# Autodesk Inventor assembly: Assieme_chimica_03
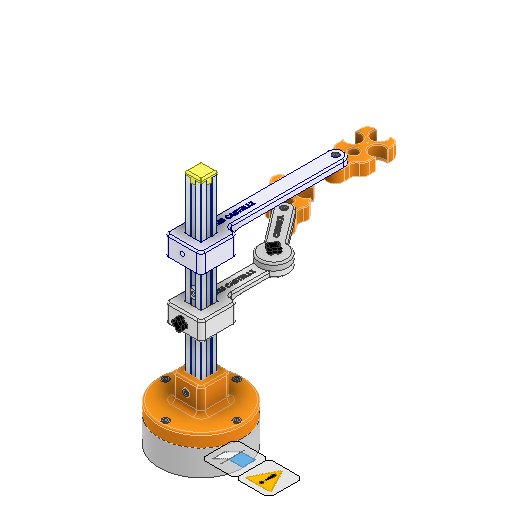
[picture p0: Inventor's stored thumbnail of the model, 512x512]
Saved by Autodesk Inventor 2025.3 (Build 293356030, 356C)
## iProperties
Created: 2025-09
Part Number: Assieme_chimica_03
Document SubType Name: Assembly
Designer: Ryzen5700u
Author: Ryzen5700u
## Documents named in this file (16)
- C:\Users\R5800u\Desktop\chimica_finale\Assieme_chimica_03.iam
- C:\Users\R5800u\Desktop\chimica_finale\tslot-20x20-3_MIR1.ipt
- C:\Users\R5800u\Desktop\chimica_finale\base_ferro.ipt
- C:\Users\R5800u\Desktop\chimica_finale\braccio.ipt
- C:\Users\R5800u\Desktop\chimica_finale\tappo_2020.ipt
- C:\Users\R5800u\Desktop\chimica_finale\vite_blocco.ipt
- C:\Users\R5800u\Desktop\chimica_finale\porta_sensore.ipt
- C:\Users\R5800u\Documents\Inventor\Content Center Files\R2025\it-IT\AS 1420\AS 1420 - 1973 - M5 x 20.ipt
- C:\Users\R5800u\Desktop\chimica_finale\AS 1420 - 1973 - M4 x 8.ipt
- C:\Users\R5800u\Desktop\chimica_finale\Slider T-Nut for 2020 - M4.ipt
- C:\Users\R5800u\Desktop\chimica_finale\base_petg2.ipt
- C:\Users\R5800u\Desktop\chimica_finale\braccio2.ipt
- C:\Users\R5800u\Documents\Inventor\Content Center Files\R2025\it-IT\AS 1420\AS 1420 - 1973 - M4 x 20.ipt
- C:\Users\R5800u\Desktop\chimica_finale\braccio_fisso.ipt
- C:\Users\R5800u\Desktop\chimica_finale\base_pesante.ipt
- C:\Users\R5800u\Desktop\chimica_finale\peso.ipt
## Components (22 placed, 15 different names)
1. tslot-20x20-3_MIR1:1
2. base_petg2:1
3. base_ferro:1 — Allineato:6
4. braccio:1
5. tappo_2020:1 — Allineato:8
6. vite_blocco:1 — Allineato:9, Coincidente:22
7. porta_sensore:1 — Angolo:2, Rotazionale:11
8. AS 1420 - Metrico M5 x 20:1 — Coincidente:6
9. AS 1420 - Metrico M5 x 20:2 — Coincidente:8
10. AS 1420 - Metrico M5 x 20:3 — Coincidente:10
11. AS 1420 - Metrico M5 x 20:4 — Coincidente:12
12. AS 1420 - Metrico M4 x 8:4 — Rotazionale:4
13. AS 1420 - Metrico M4 x 20:1 — Rotazionale:12
14. Slider T-Nut for 2020 - M4:1 — Angolo:1, Coincidente:19, Coincidente:20
15. AS 1420 - Metrico M4 x 8:5 — Rotazionale:5
16. braccio2:1 — Coincidente:26, Coincidente:27, Angolo:2, Rotazionale:11, Rotazionale:12, Rotazionale:13
17. vite_blocco:2 — Rotazionale:13
18. braccio_fisso:1 — Coincidente:28, Coincidente:29, Rotazionale:9, Rotazionale:10
19. porta_sensore:2 — Rotazionale:9
20. AS 1420 - Metrico M4 x 20:2 — Rotazionale:10
21. base_pesante:1 — Coincidente:30, Allineato:12, Coincidente:31, Rotazionale:14
22. peso:1 — Rotazionale:14
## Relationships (27: Mate 13, RevoluteJoint 8, Flush 4, Angle 2)
- Allineato:6 [Flush]: base_ferro:1
- Allineato:8 [Flush]: tappo_2020:1
- Allineato:9 [Flush]: vite_blocco:1
- Coincidente:6 [Mate]: AS 1420 - Metrico M5 x 20:1
- Coincidente:8 [Mate]: AS 1420 - Metrico M5 x 20:2
- Coincidente:10 [Mate]: AS 1420 - Metrico M5 x 20:3
- Coincidente:12 [Mate]: AS 1420 - Metrico M5 x 20:4
- Angolo:1 [Angle]: Slider T-Nut for 2020 - M4:1
- Coincidente:19 [Mate]: Slider T-Nut for 2020 - M4:1
- Coincidente:20 [Mate]: Slider T-Nut for 2020 - M4:1
- Coincidente:22 [Mate]: vite_blocco:1
- Rotazionale:4 [RevoluteJoint]: AS 1420 - Metrico M4 x 8:4
- Rotazionale:5 [RevoluteJoint]: AS 1420 - Metrico M4 x 8:5
- Coincidente:26 [Mate]: braccio2:1
- Coincidente:27 [Mate]: braccio2:1
- Angolo:2 [Angle]: porta_sensore:1 ↔ braccio2:1
- Coincidente:28 [Mate]: braccio_fisso:1
- Coincidente:29 [Mate]: braccio_fisso:1
- Rotazionale:9 [RevoluteJoint]: braccio_fisso:1 ↔ porta_sensore:2
- Rotazionale:10 [RevoluteJoint]: braccio_fisso:1 ↔ AS 1420 - Metrico M4 x 20:2
- Rotazionale:11 [RevoluteJoint]: porta_sensore:1 ↔ braccio2:1
- Rotazionale:12 [RevoluteJoint]: AS 1420 - Metrico M4 x 20:1 ↔ braccio2:1
- Rotazionale:13 [RevoluteJoint]: braccio2:1 ↔ vite_blocco:2
- Coincidente:30 [Mate]: base_pesante:1
- Allineato:12 [Flush]: base_pesante:1
- Coincidente:31 [Mate]: base_pesante:1
- Rotazionale:14 [RevoluteJoint]: base_pesante:1 ↔ peso:1
